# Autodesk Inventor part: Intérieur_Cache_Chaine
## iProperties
Created: 2008-11
Part Number: Intérieur_Cache_Chaine
Document SubType Name: Modeling
Designer: claivier
Author: claivier
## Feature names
1. Extrusion1
2. Extrusion2
3. Miroir1 [Mirror]
4. Perçage1 [Hole]
